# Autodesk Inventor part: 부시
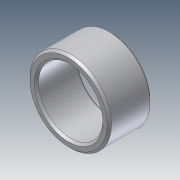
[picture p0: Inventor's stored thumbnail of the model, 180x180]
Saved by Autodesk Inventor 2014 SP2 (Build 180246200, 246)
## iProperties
Company: 한국ATC센터
Created: 2013-01
Part Number: 부시
Document SubType Name: Modeling
Designer: KYOUNG IL JANG
Density: 1 g/cm^3
Material: 일반
Appearance: 기본값
Author: KYOUNG IL JANG
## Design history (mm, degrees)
sketch "스케치1"
  geometry: L1 (15, 20)-(15, -46) reference; L2 (-20, 19)-(20, 19); L3 (30.7, -1)-(-30.7, -1) reference; L4 (19, 19)-(19, -1); L5 (15, -1)-(19, -1); L6 (0, 0)-(0, 19); L7 (19, 19)-(15, 19)
  constraints: 12 end point, 6 point on line, 1 collinear, 1 midpoint, 1 perpendicular, 1 vertical, 2 other
  dimensions: "d0" = 38 diameter of L4 L6; "d5" = 20 distance between parallel lines of L2 L3
revolve "회전1" sketch "스케치1" stored, may be unused: angle "d1" = 90 deg
chamfer "모따기1" distance "d2" = 1; stored, may be unused: second distance "d3" = 2, angle "d4" = 45 deg
node "솔리드1"
node "참조2"
